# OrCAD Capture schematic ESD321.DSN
size A; title: ESD321 1-Channel 30 kV ESD Protection Diode with Low Capacitance; rev: 1.0; note: Datasheet:SLVSEN8        EVM:NA
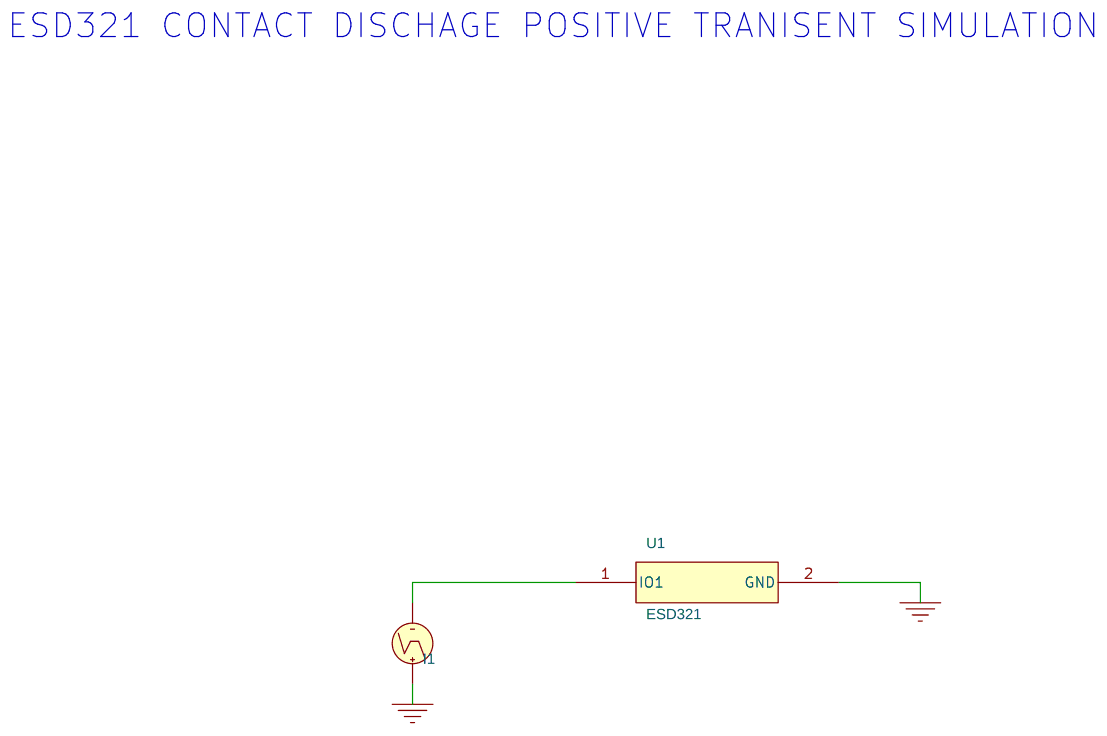
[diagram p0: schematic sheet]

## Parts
I1  IPWL_GENERIC
U1  ESD321

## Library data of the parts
I1 = IPWL_GENERIC: AppProp: No_reps$POINTS_TYPE_PWL$0$0; FIRST_NPAIRS: 0n 0 0.8n 30 6n 8 9.5n 12.5 10n 13 18n 16 22n 16 25n 16 60n 9 72n 7 82n 5.3 150n 0; PSpiceTemplate: I^@REFDES %+ %- ?DC|DC @DC| ?AC|AC @AC| PWL ?TSF|TIME_SCALE_FACTOR=@TSF| ?VSF|VALUE_SCALE_FACTOR=@VSF| ?REPEAT_VALUE| \n+ REPEAT FOR @REPEAT_VALUE| \n+ @FIRST_NPAIRS ?SECOND_NPAIRS|\n+ @SECOND_NPAIRS ?THIRD_NPAIRS/\n+ @THIRD_NPAIRS/| ?REPEAT_VALUE| \n+ ENDREPEAT|
U1 = ESD321

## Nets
0: I1.1(+) U1.2(GND)
N00385: I1.2(-) U1.1(IO1)

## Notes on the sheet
- ESD321 CONTACT DISCHAGE POSITIVE TRANISENT SIMULATION
